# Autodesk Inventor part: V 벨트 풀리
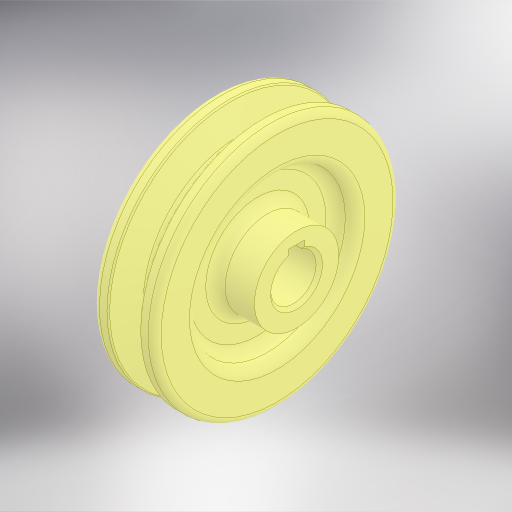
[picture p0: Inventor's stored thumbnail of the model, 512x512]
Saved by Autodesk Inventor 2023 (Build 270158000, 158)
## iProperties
Created: 2026-07
Part Number: V 벨트 풀리
Material: 강철, 주조
Document SubType Name: Modeling
Designer: home
Density: 7.85 g/cm^3
Appearance: 기본값
Author: jhkim
Sending System: Autodesk Inventor 2027
Preprocessor: ST-DEVELOPER v20.1
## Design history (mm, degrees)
feature "솔리드1"
node "솔리드2"
